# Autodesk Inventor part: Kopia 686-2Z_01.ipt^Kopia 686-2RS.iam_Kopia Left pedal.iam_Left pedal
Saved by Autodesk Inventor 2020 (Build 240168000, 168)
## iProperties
Created: 2017-10
Part Number: Kopia 686-2Z_01.ipt^Kopia 686-2RS.iam_Kopia Left pedal.iam_Left pedal
Material: Ogólny
Document SubType Name: Modeling
Designer: Tomasz
Density: 1 g/cm^3
Appearance: Domyślna
Sending System: SolidWorks 2017
Last Author: Tomasz
Last Saved: 2017-10-01
Author: Tomasz
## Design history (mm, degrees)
